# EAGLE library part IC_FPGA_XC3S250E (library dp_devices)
xc3s250e_vq100_1532 edit this description Auto generated by make-symbol-device-package-bsdl.ulp Rev. 34 Source: xc3s250e_vq100_1532.bsd
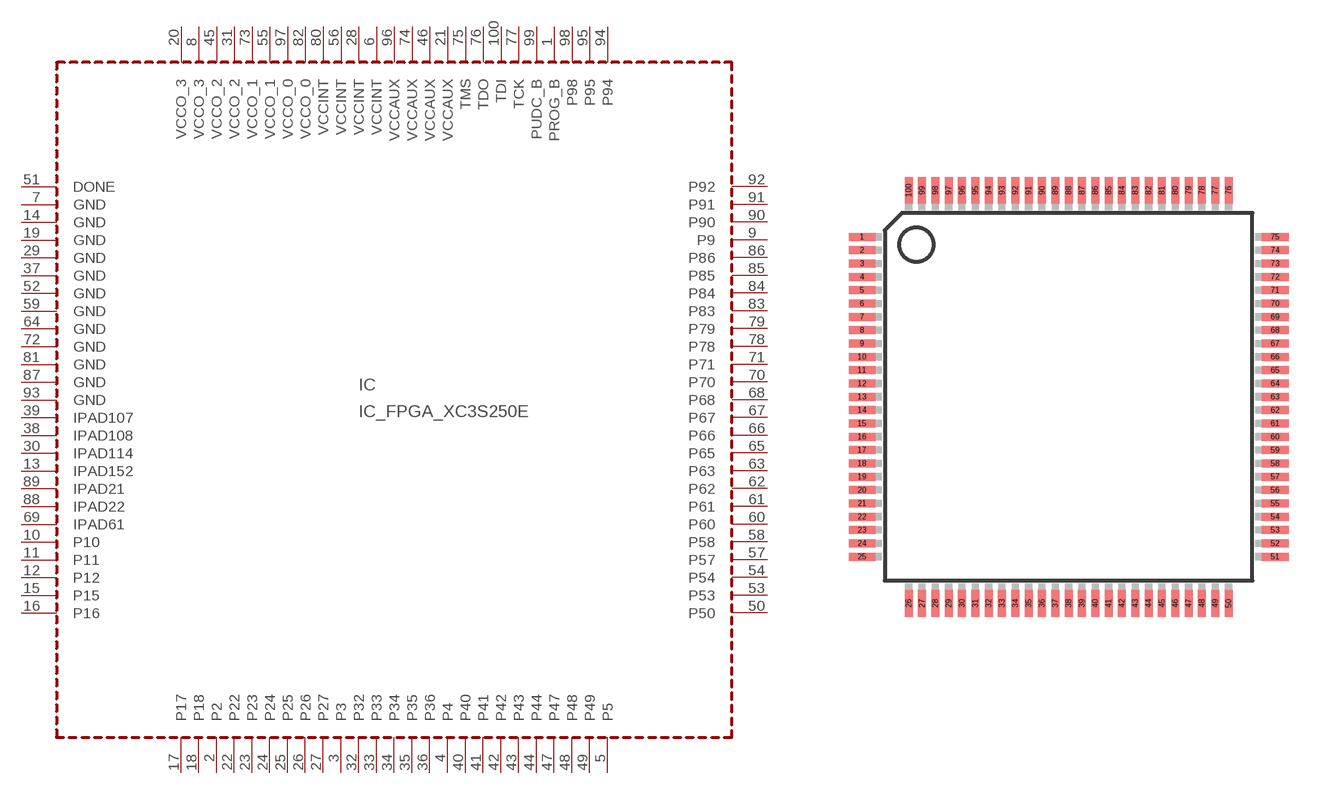
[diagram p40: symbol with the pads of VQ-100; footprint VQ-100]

Designator prefix IC

## IC_FPGA_XC3S250E  [VQ-100]
1  PROG_B  in
2  P2
3  P3
4  P4
5  P5
6  VCCINT  pwr
7  GND  pwr
8  VCCO_3  pwr
9  P9
10  P10
11  P11
12  P12
13  IPAD152  in
14  GND  pwr
15  P15
16  P16
17  P17
18  P18
19  GND  pwr
20  VCCO_3  pwr
21  VCCAUX  pwr
22  P22
23  P23
24  P24
25  P25
26  P26
27  P27
28  VCCINT  pwr
29  GND  pwr
30  IPAD114  in
31  VCCO_2  pwr
32  P32
33  P33
34  P34
35  P35
36  P36
37  GND  pwr
38  IPAD108  in
39  IPAD107  in
40  P40
41  P41
42  P42
43  P43
44  P44
45  VCCO_2  pwr
46  VCCAUX  pwr
47  P47
48  P48
49  P49
50  P50
51  DONE
52  GND  pwr
53  P53
54  P54
55  VCCO_1  pwr
56  VCCINT  pwr
57  P57
58  P58
59  GND  pwr
60  P60
61  P61
62  P62
63  P63
64  GND  pwr
65  P65
66  P66
67  P67
68  P68
69  IPAD61  in
70  P70
71  P71
72  GND  pwr
73  VCCO_1  pwr
74  VCCAUX  pwr
75  TMS  in
76  TDO  out
77  TCK  in
78  P78
79  P79
80  VCCINT  pwr
81  GND  pwr
82  VCCO_0  pwr
83  P83
84  P84
85  P85
86  P86
87  GND  pwr
88  IPAD22  in
89  IPAD21  in
90  P90
91  P91
92  P92
93  GND  pwr
94  P94
95  P95
96  VCCAUX  pwr
97  VCCO_0  pwr
98  P98
99  PUDC_B  in
100  TDI  in

## Footprint VQ-100 (pad centres in mm)
smd 1 x 0.3: 1 -7.75,6; 2 -7.75,5.5; 3 -7.75,5; 4 -7.75,4.5; 5 -7.75,4; 6 -7.75,3.5; 7 -7.75,3; 8 -7.75,2.5; 9 -7.75,2; 10 -7.75,1.5; 11 -7.75,1; 12 -7.75,0.5; 13 -7.75,0; 14 -7.75,-0.5; 15 -7.75,-1; 16 -7.75,-1.5; 17 -7.75,-2; 18 -7.75,-2.5; 19 -7.75,-3; 20 -7.75,-3.5; 21 -7.75,-4; 22 -7.75,-4.5; 23 -7.75,-5; 24 -7.75,-5.5; 25 -7.75,-6; 51 7.75,-6; 52 7.75,-5.5; 53 7.75,-5; 54 7.75,-4.5; 55 7.75,-4; 56 7.75,-3.5; 57 7.75,-3; 58 7.75,-2.5; 59 7.75,-2; 60 7.75,-1.5; 61 7.75,-1; 62 7.75,-0.5; 63 7.75,0; 64 7.75,0.5; 65 7.75,1; 66 7.75,1.5; 67 7.75,2; 68 7.75,2.5; 69 7.75,3; 70 7.75,3.5; 71 7.75,4; 72 7.75,4.5; 73 7.75,5; 74 7.75,5.5; 75 7.75,6
smd 0.3 x 1: 26 -6,-7.75; 27 -5.5,-7.75; 28 -5,-7.75; 29 -4.5,-7.75; 30 -4,-7.75; 31 -3.5,-7.75; 32 -3,-7.75; 33 -2.5,-7.75; 34 -2,-7.75; 35 -1.5,-7.75; 36 -1,-7.75; 37 -0.5,-7.75; 38 0,-7.75; 39 0.5,-7.75; 40 1,-7.75; 41 1.5,-7.75; 42 2,-7.75; 43 2.5,-7.75; 44 3,-7.75; 45 3.5,-7.75; 46 4,-7.75; 47 4.5,-7.75; 48 5,-7.75; 49 5.5,-7.75; 50 6,-7.75; 76 6,7.75; 77 5.5,7.75; 78 5,7.75; 79 4.5,7.75; 80 4,7.75; 81 3.5,7.75; 82 3,7.75; 83 2.5,7.75; 84 2,7.75; 85 1.5,7.75; 86 1,7.75; 87 0.5,7.75; 88 0,7.75; 89 -0.5,7.75; 90 -1,7.75; 91 -1.5,7.75; 92 -2,7.75; 93 -2.5,7.75; 94 -3,7.75; 95 -3.5,7.75; 96 -4,7.75; 97 -4.5,7.75; 98 -5,7.75; 99 -5.5,7.75; 100 -6,7.75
